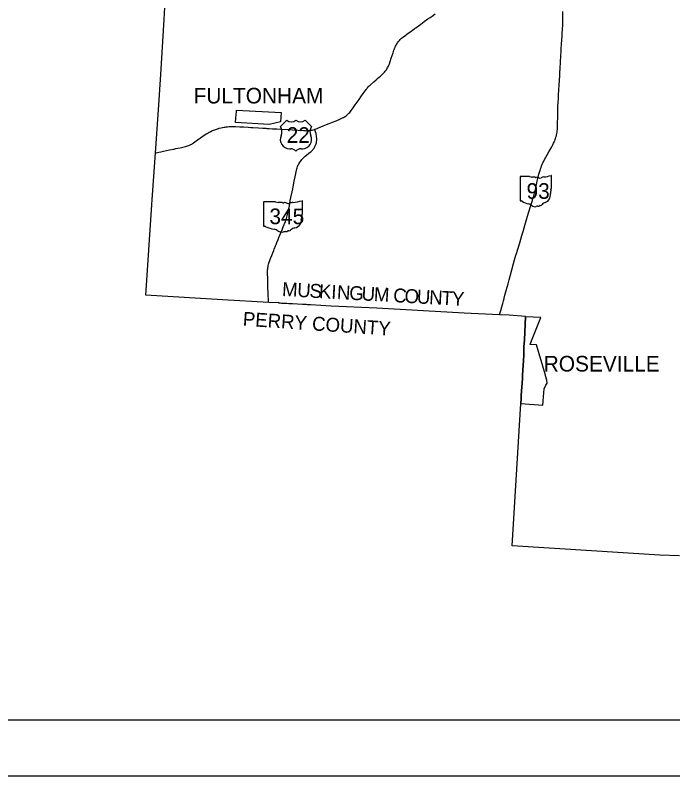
# Model space of a CAD drawing. Extents: x 2015843 to 2287843, y 623733 to 799733.
# Drawn here: x 2066735 to 2113924, y 623733 to 678304 of the extents above; entities that cross this region are included whole.
import ezdxf

# ---------------------------------------------------------------- set-up
doc = ezdxf.new("R2010")
doc.units = 0
for name, color, linetype in [('GM_X_Corporation', 7, 'Continuous'), ('GM_X_Corporation_Text', 7, 'Continuous'), ('GM_X_County', 7, 'Continuous'), ('GM_X_County_Text', 7, 'Continuous'), ('GM_X_State_Location', 7, 'Continuous'), ('GM_X_State_Route', 7, 'Continuous'), ('GM_X_State_Shield', 7, 'Continuous'), ('GM_X_US_Location', 7, 'Continuous'), ('GM_X_US_Route', 7, 'Continuous'), ('GM_X_US_Shield', 7, 'Continuous'), ('SH_Border', 7, 'Continuous'), ('SH_Cut_Line', 7, 'Continuous')]:
    doc.layers.add(name, color=color, linetype=linetype)

msp = doc.modelspace()

# ---------------------------------------------------------------- linework, layer by layer
at = {"layer": 'GM_X_Corporation'}
for p, q in [((2104454, 656616), (2103351, 656674)), ((2103779, 654932), (2104454, 656616)), ((2103678, 654689), (2103779, 654932)), ((2103696, 654683), (2103678, 654689)), ((2104138, 654660), (2103696, 654683)), ((2104785, 652468), (2104138, 654660)), ((2104796, 652429), (2104785, 652468)), ((2104890, 652114), (2104796, 652429)), ((2104687, 651488), (2104825, 651760)), ((2104825, 651760), (2104898, 651906)), ((2104898, 651906), (2104890, 652114)), ((2104631, 650643), (2104687, 651488)), ((2104609, 650316), (2104630, 650583)), ((2104630, 650583), (2104631, 650643)), ((2103024, 650438), (2104609, 650316))]:
    msp.add_line(p, q, dxfattribs=at)
msp.add_lwpolyline([(2085775, 670643), (2084959, 670461), (2082551, 670617), (2082572, 670913), (2082608, 671396), (2082612, 671485), (2085811, 671332), (2085793, 670993)], close=True, dxfattribs=at)
msp.add_lwpolyline([(2103352, 656674), (2103271, 655019), (2103258, 654759), (2103254, 654711), (2103246, 654593), (2103238, 654510), (2103235, 654461), (2103233, 654404), (2103240, 653899), (2103217, 653544), (2103213, 653519), (2103203, 653403), (2103202, 653391), (2103197, 653310), (2103192, 653245), (2103186, 653164), (2103166, 652849), (2103162, 652772), (2103162, 652768), (2103150, 652552), (2103129, 652248), (2103051, 651029), (2103052, 650812), (2103024, 650438), (2103024, 650438)], dxfattribs=at)
at = {"layer": 'GM_X_County'}
msp.add_lwpolyline([(2114403, 639504), (2113002, 639565), (2108101, 639863), (2102403, 640243), (2103024, 650438), (2103052, 650812), (2103051, 651029), (2103129, 652248), (2103150, 652552), (2103162, 652768), (2103162, 652772), (2103166, 652849), (2103186, 653164), (2103192, 653245), (2103197, 653310), (2103202, 653391), (2103203, 653403), (2103213, 653519), (2103217, 653544), (2103240, 653899), (2103233, 654404), (2103235, 654461), (2103238, 654510), (2103246, 654593), (2103254, 654711), (2103258, 654759), (2103271, 655019), (2103352, 656678), (2102192, 656777), (2101496, 656815), (2098946, 656930), (2092678, 657287), (2089409, 657433), (2087923, 657522), (2087918, 657522), (2087894, 657521), (2087813, 657524), (2087703, 657529), (2087607, 657536), (2087452, 657541), (2087439, 657541), (2087387, 657542), (2087343, 657540), (2086630, 657586), (2086495, 657591), (2086443, 657596), (2086367, 657602), (2086218, 657612), (2086038, 657620), (2085851, 657630), (2085753, 657634), (2085711, 657636), (2085686, 657640), (2085653, 657653), (2085642, 657659), (2084925, 657689), (2081605, 657885), (2076099, 658221), (2076529, 664694), (2076563, 665092), (2076802, 668417), (2077052, 671875), (2077186, 674040), (2077417, 678005), (2077491, 679285)], dxfattribs=at)
at = {"layer": 'GM_X_State_Route'}
msp.add_line((2105823, 674237), (2105829, 674332), dxfattribs=at)
for points in [[(2105898, 675462), (2105899, 675476), (2105908, 675640), (2105914, 675738), (2105923, 675918), (2105923, 675922), (2105941, 676213), (2105943, 676250), (2105961, 676511), (2105964, 676556), (2105977, 676781), (2105995, 677092), (2106001, 677197), (2106029, 677688), (2106035, 677798), (2106042, 677937), (2106042, 677947), (2106044, 678063), (2106043, 678238), (2106038, 678401), (2106034, 678559)], [(2105829, 674332), (2105831, 674363), (2105837, 674452), (2105848, 674625), (2105859, 674822), (2105866, 674920), (2105875, 675084), (2105886, 675264), (2105892, 675362), (2105898, 675462)], [(2101498, 656812), (2101582, 657124), (2101651, 657377), (2101720, 657631), (2101772, 657820), (2101815, 657979), (2101820, 657996), (2101880, 658216), (2101971, 658548), (2102100, 659023), (2102177, 659308), (2102256, 659592), (2102376, 660036), (2102501, 660495), (2102576, 660763), (2102668, 661078), (2102688, 661146), (2102936, 661974), (2103092, 662493), (2103177, 662775), (2103337, 663310), (2103407, 663545), (2103506, 663876), (2103579, 664128), (2103736, 664646), (2103821, 664928), (2103845, 665007), (2103864, 665070), (2103892, 665164), (2103921, 665258), (2103948, 665352), (2104000, 665542), (2104041, 665700), (2104064, 665796), (2104203, 666387), (2104249, 666584), (2104322, 666898), (2104359, 667041), (2104395, 667167), (2104434, 667293), (2104467, 667386), (2104508, 667493), (2104558, 667615), (2104599, 667704), (2104642, 667793), (2104703, 667909), (2105029, 668497), (2105239, 668869), (2105317, 669013), (2105369, 669115), (2105411, 669204), (2105442, 669278), (2105449, 669295), (2105485, 669386), (2105512, 669464), (2105541, 669557), (2105568, 669652), (2105587, 669731), (2105604, 669812), (2105621, 669908), (2105635, 670006), (2105645, 670103), (2105652, 670201), (2105657, 670332), (2105662, 670660), (2105666, 670890), (2105669, 671041), (2105670, 671103), (2105675, 671628), (2105680, 671792), (2105691, 672022), (2105711, 672349), (2105727, 672595), (2105746, 672922), (2105768, 673315), (2105807, 673954), (2105823, 674237)], [(2086649, 665836), (2086681, 665986), (2086764, 666403), (2086824, 666708), (2086848, 666836), (2086898, 667077), (2086923, 667189), (2086948, 667284), (2086972, 667362), (2086999, 667440), (2087024, 667500), (2087051, 667560), (2087080, 667618), (2087120, 667690), (2087163, 667759), (2087200, 667813), (2087249, 667879), (2087301, 667942), (2087355, 668003), (2087412, 668062), (2087472, 668118), (2087546, 668183), (2087634, 668256), (2087815, 668398), (2087904, 668471), (2087965, 668525), (2088013, 668570), (2088059, 668618), (2088102, 668667), (2088142, 668719), (2088180, 668773), (2088190, 668787), (2088207, 668814), (2088240, 668871), (2088270, 668930), (2088290, 668975), (2088308, 669021), (2088328, 669084), (2088345, 669148), (2088359, 669212), (2088367, 669261), (2088373, 669310), (2088375, 669360), (2088376, 669425), (2088373, 669491), (2088365, 669573), (2088354, 669654), (2088339, 669735), (2088321, 669815), (2088289, 669942), (2088246, 670088), (2088237, 670120)], [(2084926, 657687), (2084920, 657739), (2084912, 657820), (2084901, 657951), (2084889, 658147), (2084884, 658311), (2084878, 658492), (2084874, 658656), (2084873, 658721), (2084872, 658770), (2084869, 658885), (2084865, 659033), (2084853, 659459), (2084848, 659714), (2084845, 659869), (2084845, 659968), (2084849, 660033), (2084855, 660115), (2084867, 660212), (2084876, 660277), (2084892, 660357), (2084910, 660437), (2084932, 660513), (2084957, 660594), (2084997, 660702), (2085049, 660840), (2085142, 661068), (2085216, 661250), (2085289, 661433), (2085325, 661525), (2085368, 661631), (2085393, 661692), (2085417, 661753), (2085453, 661844), (2085515, 661996), (2085602, 662209), (2085659, 662349), (2085732, 662528), (2085794, 662680), (2085886, 662908), (2085972, 663121), (2086127, 663501), (2086167, 663609), (2086204, 663718), (2086232, 663813), (2086256, 663908), (2086284, 664037), (2086350, 664342), (2086384, 664519), (2086434, 664777), (2086477, 665002), (2086524, 665227), (2086605, 665623), (2086649, 665836)]]:
    msp.add_lwpolyline(points, dxfattribs=at)
at = {"layer": 'GM_X_State_Shield'}
for p, q in [((2102973, 666713), (2102973, 665012)), ((2103652, 666743), (2102995, 666743)), ((2105214, 665895), (2105214, 666785)), ((2105214, 665895), (2105214, 665895)), ((2084558, 664892), (2084558, 663190)), ((2085406, 664921), (2084586, 664921)), ((2087360, 664073), (2087360, 664963)), ((2087360, 664073), (2087360, 664073))]:
    msp.add_line(p, q, dxfattribs=at)
for centre, radius, start, end in [((2102999, 666717), 26, 98.1301, 188.1301), ((2103808, 666940), 252, 231.6195, 271.1119), ((2103891, 665788), 904, 80.4867, 94.9883), ((2104097, 666726), 72.7, 219.7921, 297.1024), ((2104203, 666529), 151, 54.4667, 119.1411), ((2104398, 666799), 182, 233.8562, 294.8282), ((2104719, 666223), 478, 97.3462, 120.7689), ((2104416, 669062), 2377, 275.8445, 288.9065), ((2105190, 666789), 25, 351.8621, 97.738), ((2105209, 665830), 38.6, 107.944, 210.337), ((2104963, 665717), 232, 340.033, 23.6496), ((2105188, 665892), 26.7, 289.6038, 7.7341), ((2104549, 665409), 595, 292.3089, 8.9858), ((2105304, 665523), 169, 136.8065, 186.9296), ((2102999, 665009), 26.2, 171.9584, 258.3066), ((2103003, 665183), 200, 267.339, 280.6039), ((2103044, 664914), 72.1, 29.7484, 93.2717), ((2103954, 666443), 1716, 240.4129, 257.1985), ((2103442, 664248), 537, 47.1842, 75.836), ((2104387, 664847), 192, 282.8732, 323.2771), ((2104800, 664535), 326, 94.4031, 142.5768), ((2104023, 664906), 341, 230.7004, 286.2918), ((2104220, 664318), 280, 85.6951, 111.2099), ((2104245, 664778), 182, 268.777, 315.5493), ((2104409, 664614), 51.1, 65.7517, 132.6484)]:
    msp.add_arc(centre, radius, start, end, dxfattribs=at)
for centre, major_axis, start_param, end_param in [((2084590, 664895), (32.5, 0), 1.712693, 3.28349), ((2085602, 665118), (315, 0), 4.042523, 4.731795), ((2085706, 663966), (1130, 0), 1.404758, 1.657858), ((2085963, 664904), (90.8, 0), 3.836095, 5.185415), ((2086096, 664707), (189, 0), 0.950623, 2.079405), ((2086340, 664977), (227, 0), 4.081561, 5.145723), ((2086741, 664401), (598, 0), 1.699011, 2.107814), ((2086362, 667240), (2971, 0), 4.814394, 5.042369), ((2087329, 664967), (31.2, 0), 6.141152, 7.989035), ((2086529, 663587), (743, 0), 5.101752, 6.440018), ((2087472, 663701), (211, 0), 2.387724, 3.262537), ((2087353, 664008), (48.3, 0), 1.883978, 3.671073), ((2087046, 663895), (290, 0), 5.934695, 6.695948), ((2087327, 664070), (33.4, 0), 5.05454, 6.418171), ((2084591, 663187), (32.7, 0), 3.00124, 4.508301), ((2084596, 663361), (250, 0), 4.665946, 4.897461), ((2084647, 663092), (90.1, 0), 0.519207, 1.627899), ((2085784, 664621), (2146, 0), 4.195997, 4.488961), ((2086842, 662713), (407, 0), 1.647645, 2.488434), ((2085145, 662426), (671, 0), 0.823519, 1.323587), ((2085871, 663084), (426, 0), 4.026481, 4.996735), ((2086117, 662496), (350, 0), 1.495662, 1.94098), ((2086148, 662956), (227, 0), 4.691044, 5.507374), ((2086353, 662792), (63.9, 0), 1.147584, 2.315152), ((2086326, 663026), (240, 0), 4.937069, 5.64225)]:
    msp.add_ellipse(centre, major_axis=major_axis, ratio=0.8, start_param=start_param, end_param=end_param, dxfattribs=at)
at = {"layer": 'GM_X_US_Route'}
for points in [[(2093954, 675890), (2093960, 675908), (2093996, 676000), (2094028, 676076), (2094064, 676149), (2094095, 676207), (2094138, 676278), (2094174, 676333), (2094212, 676387), (2094253, 676438), (2094307, 676501), (2094363, 676561), (2094410, 676606), (2094459, 676650), (2094523, 676702), (2094693, 676831), (2094945, 677015), (2095118, 677139), (2095264, 677245), (2095386, 677331), (2095430, 677363), (2095477, 677398), (2095836, 677657), (2096088, 677841), (2096354, 678033), (2096501, 678138), (2096646, 678245), (2096860, 678398)], [(2091939, 673000), (2091976, 673046), (2092018, 673096), (2092074, 673156), (2092144, 673226), (2092216, 673294), (2092474, 673522), (2092647, 673673), (2092744, 673761), (2092880, 673880), (2092942, 673933), (2093111, 674089), (2093181, 674158), (2093237, 674217), (2093291, 674279), (2093331, 674331), (2093369, 674384), (2093413, 674453), (2093455, 674523), (2093485, 674581), (2093513, 674640), (2093545, 674716), (2093586, 674823), (2093648, 674992), (2093722, 675210), (2093853, 675598), (2093917, 675784), (2093954, 675890)], [(2082553, 670319), (2082864, 670302), (2083126, 670286), (2083453, 670267), (2083633, 670255), (2083797, 670246), (2084190, 670221), (2084501, 670203), (2084713, 670191), (2084780, 670187), (2084960, 670174), (2085189, 670162), (2085516, 670143), (2085811, 670125), (2086367, 670092), (2086629, 670074), (2087431, 670026), (2087562, 670021), (2087660, 670020), (2087742, 670023), (2087823, 670028), (2087888, 670035), (2087969, 670048), (2088049, 670065), (2088128, 670085), (2088207, 670109), (2088237, 670120), (2088268, 670131), (2088405, 670186), (2088592, 670262), (2088626, 670276), (2088845, 670366), (2089073, 670458), (2089271, 670538), (2089500, 670629), (2089758, 670735), (2090031, 670845), (2090137, 670891), (2090225, 670933), (2090298, 670971), (2090354, 671004), (2090410, 671039), (2090477, 671086), (2090541, 671136), (2090591, 671178), (2090640, 671222), (2090686, 671268), (2090741, 671328), (2090794, 671391), (2090854, 671469), (2090998, 671668), (2091140, 671869), (2091272, 672057), (2091414, 672258), (2091545, 672446), (2091715, 672687), (2091857, 672889), (2091925, 672982), (2091939, 673000)], [(2076803, 668414), (2076857, 668430), (2076938, 668452), (2077044, 668476), (2077179, 668505), (2077381, 668547), (2077602, 668593), (2077816, 668638), (2078127, 668700), (2078272, 668730), (2078416, 668761), (2078577, 668794), (2078754, 668830), (2078866, 668855), (2078945, 668874), (2079024, 668898), (2079101, 668924), (2079193, 668958), (2079253, 668984), (2079327, 669019), (2079399, 669058), (2079469, 669099), (2079538, 669144), (2079632, 669209), (2079896, 669404), (2080028, 669502), (2080132, 669581), (2080226, 669648), (2080336, 669720), (2080433, 669781), (2080511, 669828), (2080663, 669908), (2080737, 669945), (2080857, 669999), (2080962, 670044), (2081070, 670086), (2081193, 670130), (2081300, 670164), (2081339, 670177), (2081382, 670188), (2081509, 670219), (2081622, 670244), (2081719, 670262), (2081793, 670276), (2081875, 670288), (2081979, 670300), (2082077, 670310), (2082208, 670318), (2082323, 670322), (2082438, 670323), (2082553, 670319)]]:
    msp.add_lwpolyline(points, dxfattribs=at)
at = {"layer": 'GM_X_US_Shield'}
for p, q in [((2086228, 670780), (2085761, 670313)), ((2088002, 670313), (2087535, 670780)), ((2086415, 668726), (2086508, 668726)), ((2087255, 668726), (2087348, 668726))]:
    msp.add_line(p, q, dxfattribs=at)
for centre, radius, start, end in [((2086555, 671114), 467, 225.573, 314.427), ((2087208, 671114), 467, 225.573, 314.427), ((2085225, 669938), 654, 334.5471, 35.0009), ((2088538, 669938), 654, 144.9991, 205.4529), ((2086407, 669380), 654, 154.8319, 270.6383), ((2087356, 669380), 654, 269.3617, 25.1681), ((2086508, 668259), 467, 36.8699, 90), ((2087255, 668259), 467, 90, 143.1301)]:
    msp.add_arc(centre, radius, start, end, dxfattribs=at)
at = {"layer": 'SH_Border'}
msp.add_lwpolyline([(2027843, 795733), (2283843, 795733), (2283843, 627733), (2027843, 627733)], close=True, dxfattribs=at)
at = {"layer": 'SH_Cut_Line'}
msp.add_lwpolyline([(2015843, 623733), (2287843, 623733), (2287843, 799733), (2015843, 799733)], close=True, dxfattribs=at)

# ---------------------------------------------------------------- texts
at = {"layer": 'GM_X_Corporation_Text'}
for s, p in [('FULTONHAM', (2079534, 671973)), ('ROSEVILLE', (2104661, 652740))]:
    msp.add_text(s, height=1120, rotation=0, dxfattribs=at).set_placement(p)
at = {"layer": 'GM_X_County_Text'}
for s, rotation, p in [('M', 356.8694, (2085866, 658156)), ('U', 356.8694, (2086952, 658096)), ('S', 356.8696, (2087835, 658048)), ('K', 356.8694, (2088511, 658011)), ('I', 356.8696, (2089394, 657963)), ('N', 356.8693, (2089803, 657940)), ('G', 356.8694, (2090686, 657892)), ('U', 356.8693, (2091569, 657844)), ('M', 356.8696, (2092452, 657796)), ('C', 356.8694, (2093841, 657720)), ('O', 356.8694, (2094653, 657675)), ('U', 356.8693, (2095536, 657627)), ('N', 356.8694, (2096419, 657579)), ('T', 356.8696, (2097303, 657530)), ('Y', 356.8475, (2098049, 657489)), ('PERRY COUNTY', 356.1283, (2083045, 656031))]:
    msp.add_text(s, height=1000, rotation=rotation, dxfattribs=at).set_placement(p)
at = {"layer": 'GM_X_State_Location'}
for s, p in [('93', (2103827, 665443)), ('345', (2085941, 663881))]:
    msp.add_text(s, height=1, rotation=0, dxfattribs=at).set_placement(p)
for s, p in [('s', (2104079, 665516)), ('r', (2104079, 665516)), ('s', (2086294, 663954)), ('r', (2086294, 663954))]:
    msp.add_text(s, height=1, dxfattribs=at).set_placement(p)
at = {"layer": 'GM_X_State_Shield'}
for s, p in [('93', (2103429, 665132)), ('345', (2084976, 663310))]:
    msp.add_text(s, height=1120.7, dxfattribs=at).set_placement(p)
at = {"layer": 'GM_X_US_Location'}
msp.add_text('22', height=1, rotation=0, dxfattribs=at).set_placement((2085655, 669689))
for s in ['0', '/']:
    msp.add_text(s, height=1, dxfattribs=at).set_placement((2085861, 669896))
at = {"layer": 'GM_X_US_Shield'}
msp.add_text('22', height=1120.7, dxfattribs=at).set_placement((2086212, 669146))

doc.saveas('drawing.dxf')
